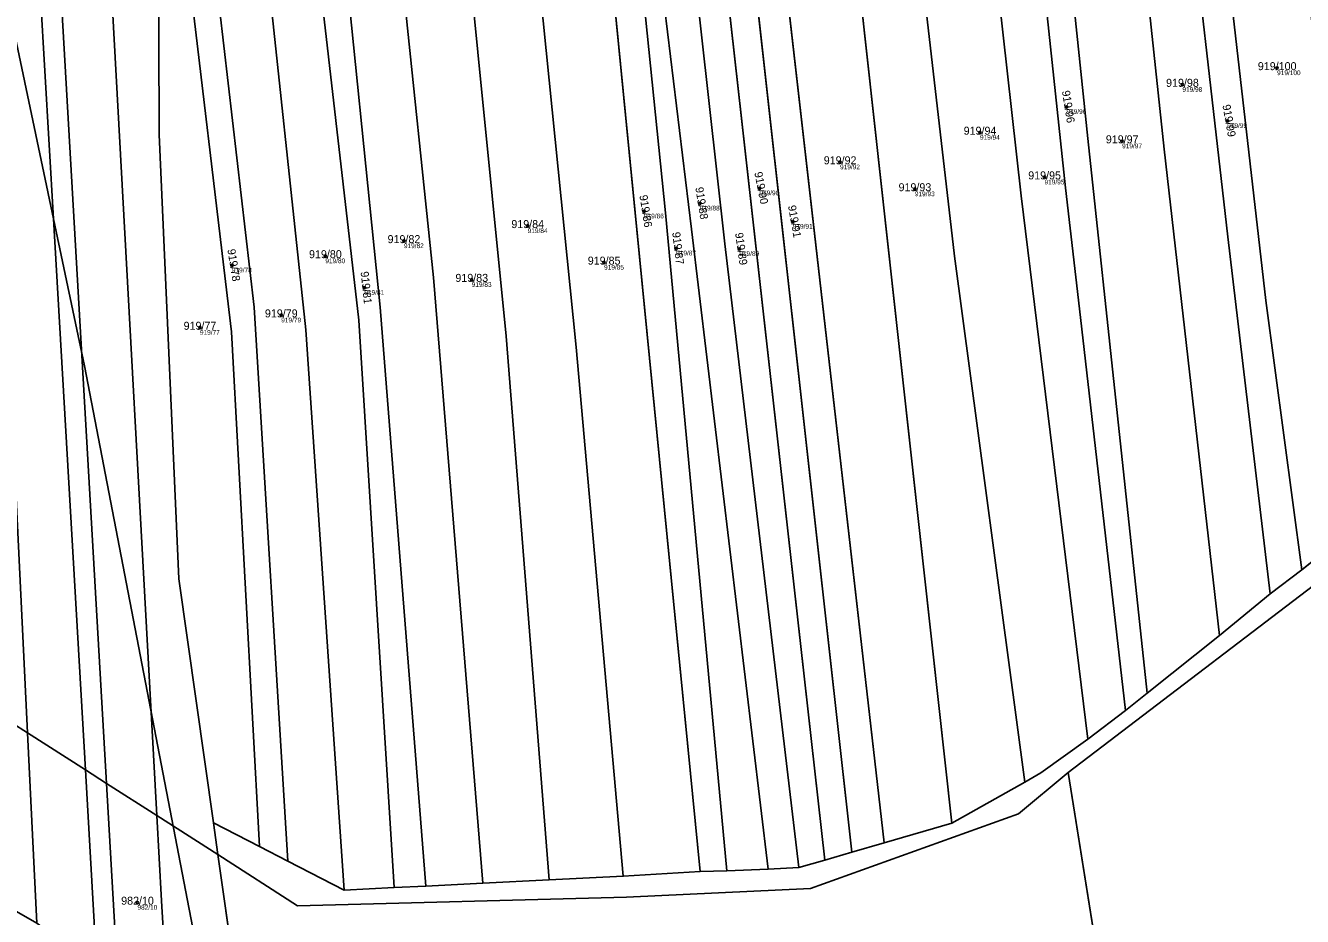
# Model space of a CAD drawing. Extents: x -603967 to -594699, y -1179315 to -1165625.
# Drawn here: x -595878.2 to -595606.9, y -1172615.3 to -1172425.9 of the extents above; entities that cross this region are included whole.
import ezdxf

# ---------------------------------------------------------------- set-up
doc = ezdxf.new("R2010")
doc.units = 0
for name, color, linetype in [('Definiční body', 7, 'Continuous'), ('Hranice parcel', 7, 'Continuous'), ('Parcelní čísla', 7, 'Continuous'), ('Polygon parcely', 7, 'Continuous'), ('Poz předměty', 7, 'Continuous'), ('Vnitřní kresba', 7, 'Continuous')]:
    doc.layers.add(name, color=color, linetype=linetype)

msp = doc.modelspace()

# ---------------------------------------------------------------- linework, layer by layer
at = {"layer": 'Definiční body'}
for centre in [(-595612.33, -1172434.97994), (-595632.45, -1172438.51994), (-595657.08, -1172443.21994), (-595622.93, -1172446.19994), (-595675.45, -1172448.69994), (-595645.25, -1172450.52994), (-595705.17, -1172454.98994), (-595661.73, -1172458.18994), (-595722.31, -1172460.49994), (-595689.28, -1172460.70994), (-595734.96, -1172463.72994), (-595746.83, -1172465.40994), (-595771.53, -1172468.53994), (-595715.22, -1172467.59994), (-595797.82, -1172471.73994), (-595814.51, -1172474.93994), (-595739.99, -1172473.27994), (-595726.57, -1172473.40994), (-595834.36, -1172476.88994), (-595755.3, -1172476.30994), (-595783.42, -1172479.96994), (-595806.23, -1172481.65994), (-595823.88, -1172487.51994), (-595841.15, -1172490.14994), (-595854.42, -1172612.32994)]:
    msp.add_circle(centre, 0.25, dxfattribs=at)
at = {"layer": 'Hranice parcel'}
for p, q in [((-595695.82, -1172599.6), (-595729.22, -1172307.12)), ((-595681.4, -1172595.41), (-595713.39, -1172306.22)), ((-595734.9, -1172605.67), (-595764.04, -1172309.77)), ((-595708.4, -1172603.26), (-595741.56, -1172308.06)), ((-595702.65, -1172601.59), (-595735.41, -1172307.6)), ((-595591.75, -1172529.36), (-595607.1, -1172541.6)), ((-595607.1, -1172541.6), (-595613.81, -1172546.71)), ((-595845.61, -1172543.49), (-595838.28, -1172595.38)), ((-595613.81, -1172546.71), (-595624.58, -1172555.55)), ((-595624.58, -1172555.55), (-595639.95, -1172567.8)), ((-595639.95, -1172567.8), (-595644.55, -1172571.49)), ((-595644.55, -1172571.49), (-595652.57, -1172577.55)), ((-595634.54, -1172723.57), (-595656.72, -1172584.67)), ((-595665.92, -1172586.69), (-595681.4, -1172595.41)), ((-595828.51, -1172600.4), (-595838.28, -1172595.38)), ((-595838.28, -1172595.38), (-595837.33, -1172602.09)), ((-595681.4, -1172595.41), (-595695.82, -1172599.6)), ((-595695.82, -1172599.6), (-595702.65, -1172601.59)), ((-595837.33, -1172602.09), (-595830.65, -1172649.32)), ((-595822.45, -1172603.51), (-595828.51, -1172600.4)), ((-595702.65, -1172601.59), (-595708.4, -1172603.26)), ((-595810.48, -1172609.66), (-595822.45, -1172603.51)), ((-595729.19, -1172605.53), (-595734.9, -1172605.67)), ((-595720.47, -1172605.19), (-595729.19, -1172605.53)), ((-595713.9, -1172604.86), (-595720.47, -1172605.19)), ((-595708.4, -1172603.26), (-595713.9, -1172604.86)), ((-595781.02, -1172608.2), (-595793.19, -1172608.8)), ((-595766.98, -1172607.5), (-595781.02, -1172608.2)), ((-595751.21, -1172606.72), (-595766.98, -1172607.5)), ((-595734.9, -1172605.67), (-595751.21, -1172606.72)), ((-595799.91, -1172609.13), (-595810.48, -1172609.66)), ((-595793.19, -1172608.8), (-595799.91, -1172609.13))]:
    msp.add_line(p, q, dxfattribs=at)
for points in [[(-595613.81, -1172546.71), (-595622.79, -1172470.79), (-595642.22, -1172301.06)], [(-595607.1, -1172541.6), (-595614.73, -1172484.39), (-595621.66, -1172423.79), (-595636.41, -1172300.57)], [(-595644.55, -1172571.49), (-595654.11, -1172487.95), (-595657.3, -1172460.43), (-595673.95, -1172303.86)], [(-595639.95, -1172567.8), (-595652.54, -1172449.94), (-595667.81, -1172303.37)], [(-595624.58, -1172555.55), (-595636.33, -1172452.22), (-595652.29, -1172301.88)], [(-595665.92, -1172586.69), (-595680.83, -1172474.95), (-595700.37, -1172305.37)], [(-595652.57, -1172577.55), (-595666.67, -1172462.12), (-595684.36, -1172304.57)], [(-595729.19, -1172605.53), (-595742.27, -1172465.71), (-595758.2, -1172309.47)], [(-595720.47, -1172605.19), (-595736.76, -1172469.19), (-595743.11, -1172416.73), (-595752.64, -1172308.9)], [(-595713.9, -1172604.86), (-595729.63, -1172472.3), (-595747.93, -1172308.54)], [(-595781.02, -1172608.2), (-595791.56, -1172479.47), (-595798.11, -1172416.19), (-595808.65, -1172312.32)], [(-595766.98, -1172607.5), (-595776.11, -1172491.96), (-595794.06, -1172311.49)], [(-595751.21, -1172606.72), (-595761.25, -1172494.24), (-595779.75, -1172310.67)], [(-595793.19, -1172608.8), (-595802.86, -1172485.78), (-595820.25, -1172314.31)], [(-595799.91, -1172609.13), (-595807.43, -1172488.53), (-595817.14, -1172403.59)], [(-595828.51, -1172600.4), (-595834.41, -1172491.04), (-595844.46, -1172407.06)], [(-595822.45, -1172603.51), (-595829.61, -1172485.78), (-595838.84, -1172406.35)], [(-595810.48, -1172609.66), (-595818.64, -1172490.59), (-595827.77, -1172404.94)], [(-595849.96, -1172407.76), (-595849.84, -1172449.1), (-595845.61, -1172543.49)], [(-595656.72, -1172584.67), (-595594.45, -1172537.17), (-595506.92, -1172476.65)], [(-595887.85, -1172569.82), (-595877.77, -1172576.26), (-595865.48, -1172584.11), (-595861.01, -1172586.97), (-595850.29, -1172593.82), (-595837.33, -1172602.09)], [(-595652.57, -1172577.55), (-595662.55, -1172584.75), (-595665.92, -1172586.69)], [(-595837.33, -1172602.09), (-595820.42, -1172613.01), (-595750.57, -1172611.13), (-595711.44, -1172609.29), (-595667.3, -1172593.42), (-595656.72, -1172584.67)]]:
    msp.add_lwpolyline(points, dxfattribs=at)
at = {"layer": 'Polygon parcely'}
for points in [[(-595887.85, -1172569.82), (-595877.77, -1172576.26), (-595865.48, -1172584.11), (-595861.01, -1172586.97), (-595850.29, -1172593.82), (-595837.33, -1172602.09), (-595838.28, -1172595.38), (-595845.61, -1172543.49), (-595849.84, -1172449.1), (-595849.96, -1172407.76), (-595854.2, -1172325.73), (-595854.43, -1172322.24), (-595854.57, -1172320.09), (-595854.83, -1172316.3), (-595855.39, -1172307.95), (-595857.2, -1172281.06), (-595857.81, -1172271.97), (-595858.12, -1172267.42), (-595868.33, -1172269.05), (-595879.14, -1172270.77)], [(-595591.75, -1172529.36), (-595607.1, -1172541.6), (-595613.81, -1172546.71), (-595624.58, -1172555.55), (-595639.95, -1172567.8), (-595644.55, -1172571.49), (-595652.57, -1172577.55), (-595662.55, -1172584.75), (-595665.92, -1172586.69), (-595681.4, -1172595.41), (-595695.82, -1172599.6), (-595702.65, -1172601.59), (-595708.4, -1172603.26), (-595713.9, -1172604.86), (-595720.47, -1172605.19), (-595729.19, -1172605.53), (-595734.9, -1172605.67), (-595751.21, -1172606.72), (-595766.98, -1172607.5), (-595781.02, -1172608.2), (-595793.19, -1172608.8), (-595799.91, -1172609.13), (-595810.48, -1172609.66), (-595822.45, -1172603.51), (-595828.51, -1172600.4), (-595838.28, -1172595.38), (-595837.33, -1172602.09), (-595820.42, -1172613.01), (-595750.57, -1172611.13), (-595711.44, -1172609.29), (-595667.3, -1172593.42), (-595656.72, -1172584.67), (-595594.45, -1172537.17)]]:
    msp.add_lwpolyline(points, dxfattribs=at)
for points in [[(-595642.22, -1172301.06), (-595652.29, -1172301.88), (-595636.33, -1172452.22), (-595624.58, -1172555.55), (-595613.81, -1172546.71), (-595622.79, -1172470.79)], [(-595621.66, -1172423.79), (-595636.41, -1172300.57), (-595642.22, -1172301.06), (-595622.79, -1172470.79), (-595613.81, -1172546.71), (-595607.1, -1172541.6), (-595614.73, -1172484.39)], [(-595591.75, -1172529.36), (-595620.82, -1172299.27), (-595636.41, -1172300.57), (-595621.66, -1172423.79), (-595614.73, -1172484.39), (-595607.1, -1172541.6)], [(-595654.11, -1172487.95), (-595657.3, -1172460.43), (-595673.95, -1172303.86), (-595684.36, -1172304.57), (-595666.67, -1172462.12), (-595652.57, -1172577.55), (-595644.55, -1172571.49)], [(-595652.54, -1172449.94), (-595667.81, -1172303.37), (-595673.95, -1172303.86), (-595657.3, -1172460.43), (-595654.11, -1172487.95), (-595644.55, -1172571.49), (-595639.95, -1172567.8)], [(-595636.33, -1172452.22), (-595652.29, -1172301.88), (-595667.81, -1172303.37), (-595652.54, -1172449.94), (-595639.95, -1172567.8), (-595624.58, -1172555.55)], [(-595729.22, -1172307.12), (-595735.41, -1172307.6), (-595702.65, -1172601.59), (-595695.82, -1172599.6)], [(-595681.4, -1172595.41), (-595713.39, -1172306.22), (-595729.22, -1172307.12), (-595695.82, -1172599.6)], [(-595700.37, -1172305.37), (-595713.39, -1172306.22), (-595681.4, -1172595.41), (-595665.92, -1172586.69), (-595680.83, -1172474.95)], [(-595684.36, -1172304.57), (-595700.37, -1172305.37), (-595680.83, -1172474.95), (-595665.92, -1172586.69), (-595662.55, -1172584.75), (-595652.57, -1172577.55), (-595666.67, -1172462.12)], [(-595779.75, -1172310.67), (-595761.25, -1172494.24), (-595751.21, -1172606.72), (-595734.9, -1172605.67), (-595764.04, -1172309.77)], [(-595758.2, -1172309.47), (-595764.04, -1172309.77), (-595734.9, -1172605.67), (-595729.19, -1172605.53), (-595742.27, -1172465.71)], [(-595752.64, -1172308.9), (-595758.2, -1172309.47), (-595742.27, -1172465.71), (-595729.19, -1172605.53), (-595720.47, -1172605.19), (-595736.76, -1172469.19), (-595743.11, -1172416.73)], [(-595729.63, -1172472.3), (-595747.93, -1172308.54), (-595752.64, -1172308.9), (-595743.11, -1172416.73), (-595736.76, -1172469.19), (-595720.47, -1172605.19), (-595713.9, -1172604.86)], [(-595741.56, -1172308.06), (-595747.93, -1172308.54), (-595729.63, -1172472.3), (-595713.9, -1172604.86), (-595708.4, -1172603.26)], [(-595735.41, -1172307.6), (-595741.56, -1172308.06), (-595708.4, -1172603.26), (-595702.65, -1172601.59)], [(-595781.02, -1172608.2), (-595791.56, -1172479.47), (-595798.11, -1172416.19), (-595808.65, -1172312.32), (-595820.25, -1172314.31), (-595802.86, -1172485.78), (-595793.19, -1172608.8)], [(-595794.06, -1172311.49), (-595808.65, -1172312.32), (-595798.11, -1172416.19), (-595791.56, -1172479.47), (-595781.02, -1172608.2), (-595766.98, -1172607.5), (-595776.11, -1172491.96)], [(-595779.75, -1172310.67), (-595794.06, -1172311.49), (-595776.11, -1172491.96), (-595766.98, -1172607.5), (-595751.21, -1172606.72), (-595761.25, -1172494.24)], [(-595793.19, -1172608.8), (-595802.86, -1172485.78), (-595820.25, -1172314.31), (-595827.17, -1172315.88), (-595826.05, -1172325.65), (-595823.5, -1172325.91), (-595818.04, -1172374.6), (-595815.21, -1172403.34), (-595817.14, -1172403.59), (-595807.43, -1172488.53), (-595799.91, -1172609.13)], [(-595807.43, -1172488.53), (-595817.14, -1172403.59), (-595827.77, -1172404.94), (-595818.64, -1172490.59), (-595810.48, -1172609.66), (-595799.91, -1172609.13)], [(-595834.41, -1172491.04), (-595844.46, -1172407.06), (-595849.96, -1172407.76), (-595849.84, -1172449.1), (-595845.61, -1172543.49), (-595838.28, -1172595.38), (-595828.51, -1172600.4)], [(-595822.45, -1172603.51), (-595829.61, -1172485.78), (-595838.84, -1172406.35), (-595844.46, -1172407.06), (-595834.41, -1172491.04), (-595828.51, -1172600.4)], [(-595818.64, -1172490.59), (-595827.77, -1172404.94), (-595838.84, -1172406.35), (-595829.61, -1172485.78), (-595822.45, -1172603.51), (-595810.48, -1172609.66)], [(-595334.34, -1172549.64), (-595506.92, -1172476.65), (-595594.45, -1172537.17), (-595656.72, -1172584.67), (-595634.54, -1172723.57), (-595614.81, -1172722.22), (-595483.51, -1172712), (-595470.07, -1172710.46), (-595454.54, -1172706.46), (-595434.58, -1172699.02), (-595419, -1172690.38), (-595402.9, -1172678.28), (-595390.62, -1172666.92), (-595381.58, -1172655.2), (-595373.33, -1172643.44), (-595365.3, -1172627.41)], [(-595888.79, -1172609.27), (-595875.83, -1172616.67), (-595863.05, -1172626.07), (-595858.57, -1172629.37), (-595847.81, -1172637.28), (-595846.32, -1172638.37), (-595830.65, -1172649.32), (-595837.33, -1172602.09), (-595850.29, -1172593.82), (-595861.01, -1172586.97), (-595865.48, -1172584.11), (-595877.77, -1172576.26), (-595887.85, -1172569.82)], [(-595634.54, -1172723.57), (-595656.72, -1172584.67), (-595667.3, -1172593.42), (-595711.44, -1172609.29), (-595750.57, -1172611.13), (-595820.42, -1172613.01), (-595837.33, -1172602.09), (-595830.65, -1172649.32), (-595846.32, -1172638.37), (-595846.18, -1172640.59), (-595766.83, -1172696.64), (-595751.84, -1172703.56), (-595738.47, -1172709.91), (-595722.78, -1172715.71), (-595709.7, -1172719.14), (-595696.38, -1172722.38), (-595681.97, -1172724.22), (-595667.37, -1172724.76), (-595652.24, -1172724.79)]]:
    msp.add_lwpolyline(points, close=True, dxfattribs=at)
at = {"layer": 'Poz předměty'}
for p, q in [((-595900.85, -1172331.16), (-595872.26, -1172467)), ((-595872.26, -1172467), (-595865.69, -1172498.22)), ((-595865.69, -1172498.22), (-595837.82, -1172642.62))]:
    msp.add_line(p, q, dxfattribs=at)
at = {"layer": 'Vnitřní kresba'}
for p, q in [((-595872.26, -1172467), (-595883.58, -1172271.48)), ((-595865.25, -1172321.68), (-595850.29, -1172593.82)), ((-595861.01, -1172586.97), (-595874.36, -1172355.21)), ((-595865.48, -1172584.11), (-595872.26, -1172467)), ((-595881.79, -1172492.57), (-595877.77, -1172576.26)), ((-595877.77, -1172576.26), (-595875.83, -1172616.67)), ((-595863.05, -1172626.07), (-595865.48, -1172584.11)), ((-595858.57, -1172629.37), (-595861.01, -1172586.97)), ((-595850.29, -1172593.82), (-595849.29, -1172611.94)), ((-595849.29, -1172611.94), (-595847.81, -1172637.28))]:
    msp.add_line(p, q, dxfattribs=at)

# ---------------------------------------------------------------- texts
at = {"layer": 'Definiční body'}
for s, p in [('919/100', (-595612.33, -1172436.469)), ('919/98', (-595632.45, -1172440.009)), ('919/96', (-595657.08, -1172444.709)), ('919/99', (-595622.93, -1172447.689)), ('919/94', (-595675.45, -1172450.189)), ('919/97', (-595645.25, -1172452.019)), ('919/92', (-595705.17, -1172456.479)), ('919/95', (-595661.73, -1172459.679)), ('919/90', (-595722.31, -1172461.989)), ('919/93', (-595689.28, -1172462.199)), ('919/88', (-595734.96, -1172465.219)), ('919/86', (-595746.83, -1172466.899)), ('919/84', (-595771.53, -1172470.029)), ('919/91', (-595715.22, -1172469.089)), ('919/82', (-595797.82, -1172473.229)), ('919/80', (-595814.51, -1172476.429)), ('919/87', (-595739.99, -1172474.769)), ('919/89', (-595726.57, -1172474.899)), ('919/78', (-595834.36, -1172478.379)), ('919/85', (-595755.3, -1172477.799)), ('919/83', (-595783.42, -1172481.459)), ('919/81', (-595806.23, -1172483.149)), ('919/79', (-595823.88, -1172489.009)), ('919/77', (-595841.15, -1172491.639)), ('982/10', (-595854.42, -1172613.819))]:
    msp.add_text(s, height=0.999996, dxfattribs=at).set_placement(p)
at = {"layer": 'Parcelní čísla'}
for s, p in [('919/100', (-595616.426, -1172435.405)), ('919/98', (-595635.916, -1172438.945)), ('919/94', (-595678.916, -1172449.125)), ('919/97', (-595648.716, -1172450.955)), ('919/92', (-595708.636, -1172455.415)), ('919/95', (-595665.196, -1172458.615)), ('919/93', (-595692.746, -1172461.135)), ('919/84', (-595774.996, -1172468.965)), ('919/82', (-595801.286, -1172472.165)), ('919/80', (-595817.976, -1172475.365)), ('919/85', (-595758.766, -1172476.735)), ('919/83', (-595786.886, -1172480.395)), ('919/79', (-595827.346, -1172487.945)), ('919/77', (-595844.616, -1172490.575)), ('982/10', (-595857.886, -1172612.755))]:
    msp.add_text(s, height=1.699998, dxfattribs=at).set_placement(p)
for s, rotation, p in [('919/96', 279, (-595658.042, -1172439.862)), ('919/99', 280, (-595623.95, -1172442.86)), ('919/90', 281, (-595723.388, -1172457.178)), ('919/88', 279, (-595735.922, -1172460.372)), ('919/86', 279, (-595747.792, -1172462.052)), ('919/91', 280, (-595716.24, -1172464.26)), ('919/87', 277, (-595740.834, -1172469.891)), ('919/89', 278, (-595727.473, -1172470.036)), ('919/78', 279, (-595835.322, -1172473.532)), ('919/81', 275.9999972, (-595807.015, -1172478.257))]:
    msp.add_text(s, height=1.699998, rotation=rotation, dxfattribs=at).set_placement(p)

doc.saveas('drawing.dxf')
